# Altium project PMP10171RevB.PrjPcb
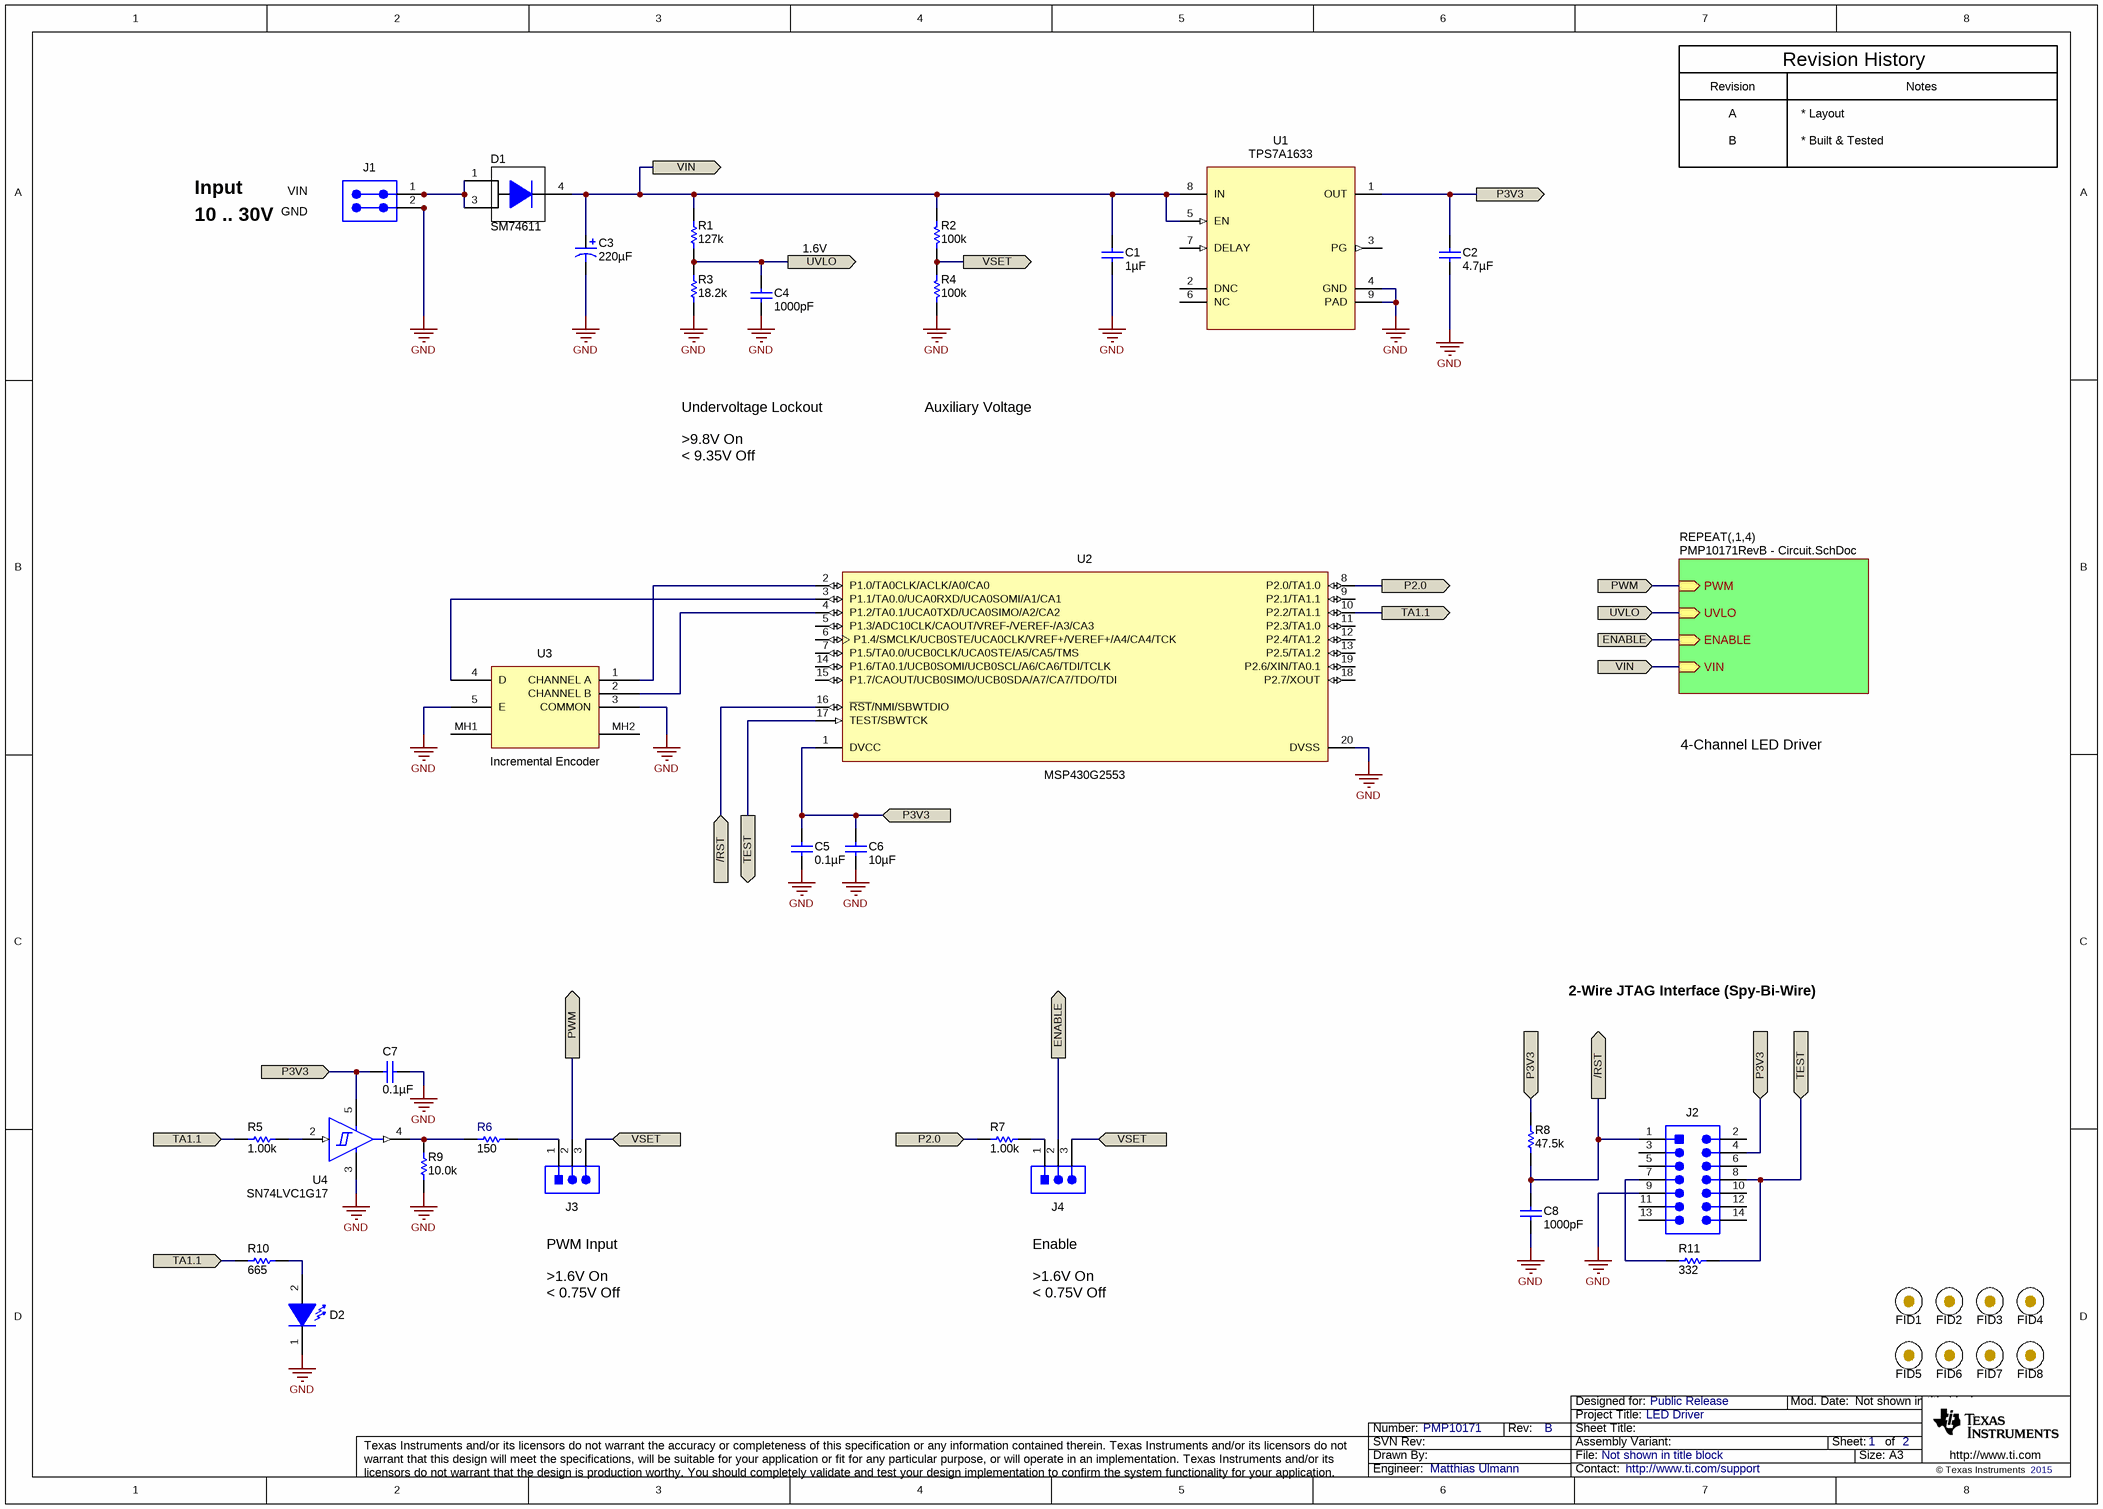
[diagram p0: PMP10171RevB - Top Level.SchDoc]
TechSupport: http://www.ti.com/support; SCH_Rev: B; PRJ_Title: LED Driver; PRJ_Number: PMP10171; PRJ_Engineer: Matthias Ulmann; PRJ_Customer: Public Release; PCB_Rev: A; PCB_Layout: M. Ulmann; CopyrightYear: 2015
2 sheets, 161 parts. Net scope: hierarchical (ports join the sheet entries above them; power ports are global).
Sheets:
  PMP10171RevB - Top Level.SchDoc
    1 = PMP10171RevB - Circuit.SchDoc
    2 = PMP10171RevB - Circuit.SchDoc
    3 = PMP10171RevB - Circuit.SchDoc
    4 = PMP10171RevB - Circuit.SchDoc

## Sheet PMP10171RevB - Top Level.SchDoc
size A3; Date: Not shown in title block; ApprovedBy: Not shown in title block; CheckedBy: Not shown in title block; Author: Not shown in title block; CompanyName: Not shown in title block; Engineer: Not shown in title block; Organization: Not shown in title block; Address1: Not shown in title block; Address2: Not shown in title block; Address3: Not shown in title block; Address4: Not shown in title block; DocumentNumber: 1; Revision: Use project parameter SCH_Rev; SheetNumber: 1; SheetTotal: 2; PageSetup: Record=PageOptions|CenterHorizontal=True|CenterVertical=True|PrintScale=0.97|XCorrection=1.00|YCorrection=1.00|PrintKind=0|BorderSize=5000000|LeftOffset=0|BottomOffset=0|Orientation=2|PaperLength=1000|PaperWidth=1000|Scale=100|PaperSource=15|PrintQuality=600|MediaType=1|DitherType=10|PaperKind=A4|PrintScaleMode=1

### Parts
C1  ValueDisplayed: 1µF  [1206]  (hidden comment: GRM31MR71H105KA88L)
C2  ValueDisplayed: 4.7µF  [0805_HV]  (hidden comment: GRM21BR71A475KA73L)
C3  ValueDisplayed: 220µF  [SM_RADIAL_G]  (hidden comment: EEE-FK1H221P)
C4  ValueDisplayed: 1000pF  [0603]  (hidden comment: GRM188R71H102KA01D)
C5  ValueDisplayed: 0.1µF  [0603]  (hidden comment: C0603C104K5RACTU)
C6  ValueDisplayed: 10µF  [0603]  (hidden comment: GRM188R60J106ME47D)
C7  ValueDisplayed: 0.1µF  [0603]  (hidden comment: C0603C104K5RACTU)
C8  ValueDisplayed: 1000pF  [0603]  (hidden comment: GRM188R71H102KA01D)
D1  SM74611  [DDPAK]
D2  150060SS75000  [WL-SMCW_RED]  (value not drawn)
FID1  Fiducial  [Fiducial10-30]  (value not drawn)
FID2  Fiducial  [Fiducial10-30]  (value not drawn)
FID3  Fiducial  [Fiducial10-30]  (value not drawn)
FID4  Fiducial  [Fiducial10-30]  (value not drawn)
FID5  Fiducial  [Fiducial10-30]  (value not drawn)
FID6  Fiducial  [Fiducial10-30]  (value not drawn)
FID7  Fiducial  [Fiducial10-30]  (value not drawn)
FID8  Fiducial  [Fiducial10-30]  (value not drawn)
J1  691 401 710 002B  [Wurth_691 401 710 002B]  (value not drawn)
J2  SBH11-PBPC-D07-ST-BK  [CONN_SBH11-PBPC-D07-ST-BK]  (value not drawn)
J3  61300311121  [WURTH_61300311121]  (value not drawn)
J4  61300311121  [WURTH_61300311121]  (value not drawn)
R1  ValueDisplayed: 127k  [0603]  (hidden comment: CRCW0603127KFKEA)
R2  ValueDisplayed: 100k  [0603]  (hidden comment: CRCW0603100KFKEA)
R3  ValueDisplayed: 18.2k  [0603]  (hidden comment: CRCW060318K2FKEA)
R4  ValueDisplayed: 100k  [0603]  (hidden comment: CRCW0603100KFKEA)
R5  ValueDisplayed: 1.00k  [0603]  (hidden comment: CRCW06031K00FKEA)
R6  ValueDisplayed: 150  [0603]  (hidden comment: CRCW0603150RFKEA)
R7  ValueDisplayed: 1.00k  [0603]  (hidden comment: CRCW06031K00FKEA)
R8  ValueDisplayed: 47.5k  [0603]  (hidden comment: CRCW060347K5FKEA)
R9  ValueDisplayed: 10.0k  [0603]  (hidden comment: CRCW060310K0FKEA)
R10  ValueDisplayed: 665  [0603]  (hidden comment: CRCW0603665RFKEA)
R11  ValueDisplayed: 332  [0603]  (hidden comment: CRCW0603332RFKEA)
U1  TPS7A1633  [DGN0008C_N]
U2  MSP430G2553  [PW0020A_N]
U3  Incremental Encoder  [Bourns_PEC16-2xxxF-Sxxx]
U4  SN74LVC1G17  [DCK0005A_N]

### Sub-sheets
REPEAT(,1,4) = PMP10171RevB - Circuit.SchDoc: PWM (in), UVLO (in), ENABLE (in), VIN (in)

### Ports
/RST (in), /RST (out), ENABLE, ENABLE (out), P2.0 (in), P2.0 (out), P3V3 (in), P3V3 (out), PWM, PWM (out), TA1.1 (in), TA1.1 (out), TEST (in), TEST (out), UVLO, UVLO (out), VIN, VIN (out), VSET (in), VSET (out)

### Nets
GND: C1.2 C2.2 C3.2(-) C4.2 C5.2 C6.2 C7.2 C8.2 D2.1(K) J1.2 J1.2A J2.9 R3.1 R4.1 R9.1 U1.4(GND) U1.9(PAD) U2.20(DVSS) U3.3(COMMON) U3.5(E) U4.3(GND)
/RST: C8.1 J2.1 R8.1 U2.16(~{RST}/NMI/SBWTDIO) ; port /RST
ENABLE: J4.2 ; port ENABLE, sheet REPEAT(,1,4)/ENABLE
P2.0: R7.1 U2.8(P2.0/TA1.0) ; port P2.0
P3V3: C2.1 C5.1 C6.1 C7.1 J2.4 R8.2 U1.1(OUT) U2.1(DVCC) U4.5(VCC) ; port P3V3
PWM: J3.2 ; port PWM, sheet REPEAT(,1,4)/PWM
TA1.1: R5.1 R10.1 U2.10(P2.2/TA1.1) ; port TA1.1
TEST: J2.8 R11.2 U2.17(TEST/SBWTCK) ; port TEST
UVLO: C4.1 R1.1 R3.2 ; port UVLO, sheet REPEAT(,1,4)/UVLO
VIN: C1.1 C3.1(+) D1.4(K) R1.2 R2.2 U1.5(EN) U1.8(IN) ; port VIN, sheet REPEAT(,1,4)/VIN
VSET: J3.3 J4.3 R2.1 R4.2 ; port VSET
NetD1_1: D1.1(A) D1.3(A) J1.1 J1.1A
NetD2_2: D2.2(A) R10.2
NetJ2_7: J2.7 R11.1
NetJ3_1: J3.1 R6.2
NetJ4_1: J4.1 R7.2
NetR5_2: R5.2 U4.2(A)
NetR6_1: R6.1 R9.2 U4.4(Y)
NetU2_2: U2.2(P1.0/TA0CLK/ACLK/A0/CA0) U3.1(CHANNEL_A)
NetU2_3: U2.3(P1.1/TA0.0/UCA0RXD/UCA0SOMI/A1/CA1) U3.4(D)
NetU2_4: U2.4(P1.2/TA0.1/UCA0TXD/UCA0SIMO/A2/CA2) U3.2(CHANNEL_B)

Not connected (* = marked no-connect by the designer): J2 2 3 5 6 10 11 12 13 14; U1 2(DNC) 3(PG) 6(NC) 7(DELAY); U2 5(P1.3/ADC10CLK/CAOUT/VREF-/VEREF-/A3/CA3) 6(P1.4/SMCLK/UCB0STE/UCA0CLK/VREF+/VEREF+/A4/CA4/TCK) 7(P1.5/TA0.0/UCB0CLK/UCA0STE/A5/CA5/TMS) 9(P2.1/TA1.1) 11(P2.3/TA1.0) 12(P2.4/TA1.2) 13(P2.5/TA1.2) 14(P1.6/TA0.1/UCB0SOMI/UCB0SCL/A6/CA6/TDI/TCLK) 15(P1.7/CAOUT/UCB0SIMO/UCB0SDA/A7/CA7/TDO/TDI) 18(P2.7/XOUT) 19(P2.6/XIN/TA0.1); U3 MH1 MH2

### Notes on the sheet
- Revision
- A
- * Layout
- Revision History
- Notes
- Input
- B
- * Built & Tested
- 10 .. 30V
- VIN
- GND
- (near C4) 1.6V
- Auxiliary Voltage
- Undervoltage Lockout
  >9.8V	On
  < 9.35V	Off
- 4-Channel LED Driver
- 2-Wire JTAG Interface (Spy-Bi-Wire)
- PWM Input
  >1.6V	On
  < 0.75V	Off
- Enable
  >1.6V	On
  < 0.75V	Off

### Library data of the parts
C1 = GRM31MR71H105KA88L: CAP, CERM, 1 µF, 50 V, +/- 10%, X7R, 1206; Manufacturer: MuRata; Polarized: N; CompType: Capacitor; Value: 1uF; U/M: EA; Cap_F: 0.000001; Tolerance_%: 10; Value1: Unknown; VDC_V: 50; Value2: 50V; TaMin_C: -55; TaMax_C: 125
C2 = GRM21BR71A475KA73L: CAP, CERM, 4.7 µF, 10 V, +/- 10%, X7R, 0805; Manufacturer: MuRata; Polarized: N; CompType: Capacitor; Value: 4.7uF; U/M: EA; Cap_F: 0.0000047; Tolerance_%: 10; Value1: Unknown; Value2: 10V; TaMin_C: -55; TaMax_C: 125; Cap_Case: 0805
C3 = EEE-FK1H221P: CAP, AL, 220 µF, 50 V, +/- 20%, 0.18 ohm, SMD; Manufacturer: Panasonic; Polarized: Y; CompType: Capacitor; Value: 220uF; U/M: EA; Cap_F: 0.00022; Tolerance_%: 20; VDC_V: 50; Value2: 50V; ESR_ohm: 0.18; IRMS_A: 0.67; TaMin_C: -55; TaMax_C: 105; Cap_Case: G
C4 C8 = GRM188R71H102KA01D: CAP, CERM, 1000 pF, 50 V, +/- 10%, X7R, 0603; Manufacturer: MuRata; Polarized: N; CompType: Capacitor; Value: 1000pF; U/M: EA; Cap_F: 0.000000001; Tolerance_%: 10; Value1: Unknown; VDC_V: 50; Value2: 50V; TaMin_C: -55; TaMax_C: 125
C5 C7 = C0603C104K5RACTU: CAP, CERM, 0.1 µF, 50 V, +/- 10%, X7R, 0603; Manufacturer: Kemet; Polarized: N; CompType: Capacitor; Value: 0.1uF; U/M: EA; Cap_F: 0.0000001; Tolerance_%: 10; Value1: Unknown; VDC_V: 50; Value2: 50V; TaMin_C: -55; TaMax_C: 125
C6 = GRM188R60J106ME47D: CAP, CERM, 10 µF, 6.3 V, +/- 20%, X5R, 0603; Manufacturer: MuRata; Polarized: N; CompType: Capacitor; Value: 10uF; U/M: EA; Cap_F: 0.00001; Tolerance_%: 20; ESR_ohm: 0.009; Value1: 0.009 ohm; VDC_V: 6.3; Value2: 6.3V; IRMS_A: 2.74; TaMin_C: -55; TaMax_C: 125
D1 = SM74611KTTR: Diode, P-N, 28 V, 15 A, DDPAK; Manufacturer: Texas Instruments; SymbolCreator: a0411947; U/M: EA; Vf_V: 0.026; Value: 28V; Value1: 15A; Value2: 0.026V; Io_A: 15; Vr_V: 28; TJmax_C: 125; RJC_CperW: 0.5
D2 = 150060SS75000: LED, Super Red, SMD; Manufacturer: Wurth Elektronik eiSos; Type: AlInGaP; Vf_V: 1.9; Value2: 1.9V; Io_A: 0.02; Value1: W; U/M: EA
FID1-FID8 = Fiducial: Fiducial mark.  There is nothing to buy or mount.; SymbolCreator: codlsc
J1 = 691 401 710 002B: Terminal Block, 1x2,  Tin, TH; Manufacturer: Wurth Elektronik; SymbolCreator: a0411947; U/M: EA
J2 = SBH11-PBPC-D07-ST-BK: Header (shrouded), 100 mil, 7x2, Gold, TH; Manufacturer: Sullins Connector Solutions; SymbolCreator: a0412235; U/M: EA
J3 J4 = 61300311121: Header, 2.54 mm, 3x1, Gold, TH; Manufacturer: Wurth Elektronik eiSos; SymbolCreator: a0799628; U/M: EA
R1 = CRCW0603127KFKEA: RES, 127 k, 1%, 0.1 W, 0603; Manufacturer: Vishay-Dale; CompType: Resistor; Value: 127k; Res_ohm: 127000; Tolerance_%: 1; Power_W: 0.1; Value2: 0.1W; VDC_V: 75; TempCo: 100 ppm/C; EIA_Code: E96; U/M: EA
R2 R4 = CRCW0603100KFKEA: RES, 100 k, 1%, 0.1 W, 0603; Manufacturer: Vishay-Dale; CompType: Resistor; Value: 100k; Res_ohm: 100000; Tolerance_%: 1; Power_W: 0.1; Value2: 0.1W; VDC_V: 75; TempCo: 100 ppm/C; EIA_Code: E96; U/M: EA
R3 = CRCW060318K2FKEA: RES, 18.2 k, 1%, 0.1 W, 0603; Manufacturer: Vishay-Dale; CompType: Resistor; Value: 18.2k; Res_ohm: 18200; Value_Code: 18k2; Tolerance_%: 1; Power_W: 0.1; Value2: 0.1W; VDC_V: 75; TempCo: 100 ppm/C; EIA_Code: E96; U/M: EA
R5 R7 = CRCW06031K00FKEA: RES, 1.00 k, 1%, 0.1 W, 0603; Manufacturer: Vishay-Dale; CompType: Resistor; Value: 1.00k; Res_ohm: 1000; Value_Code: 1k00; Tolerance_%: 1; Power_W: 0.1; Value2: 0.1W; VDC_V: 75; TempCo: 100 ppm/C; EIA_Code: E96; U/M: EA
R6 = CRCW0603150RFKEA: RES, 150, 1%, 0.1 W, 0603; Manufacturer: Vishay-Dale; CompType: Resistor; Value: 150; Value_Code: 150R; Tolerance_%: 1; Power_W: 0.1; Value2: 0.1W; VDC_V: 75; TempCo: 100 ppm/C; EIA_Code: E96; U/M: EA
R8 = CRCW060347K5FKEA: RES, 47.5 k, 1%, 0.1 W, 0603; Manufacturer: Vishay-Dale; CompType: Resistor; Value: 47.5k; Res_ohm: 47500; Value_Code: 47k5; Tolerance_%: 1; Power_W: 0.1; Value2: 0.1W; VDC_V: 75; TempCo: 100 ppm/C; EIA_Code: E96; U/M: EA
R9 = CRCW060310K0FKEA: RES, 10.0 k, 1%, 0.1 W, 0603; Manufacturer: Vishay-Dale; CompType: Resistor; Value: 10.0k; Res_ohm: 10000; Value_Code: 10k0; Tolerance_%: 1; Power_W: 0.1; Value2: 0.1W; VDC_V: 75; TempCo: 100 ppm/C; EIA_Code: E96; U/M: EA
R10 = CRCW0603665RFKEA: RES, 665, 1%, 0.1 W, 0603; Manufacturer: Vishay-Dale; CompType: Resistor; Value: 665; Value_Code: 665R; Tolerance_%: 1; Power_W: 0.1; Value2: 0.1W; VDC_V: 75; TempCo: 100 ppm/C; EIA_Code: E96; U/M: EA
R11 = CRCW0603332RFKEA: RES, 332, 1%, 0.1 W, 0603; Manufacturer: Vishay-Dale; CompType: Resistor; Value: 332; Value_Code: 332R; Tolerance_%: 1; Power_W: 0.1; Value2: 0.1W; VDC_V: 75; TempCo: 100 ppm/C; EIA_Code: E96; U/M: EA
U1 = TPS7A1633DGN: 60-V, 5-µA IQ, 100-mA, Low-Dropout Voltage Regulator with Enable and Power-Good, DGN0008C; Manufacturer: Texas Instruments; SymbolCreator: a0411947; CompType: IC; U/M: EA
U2 = MSP430G2553IPW20: Mixed Signal Microcontroller, PW0020A; Manufacturer: Texas Instruments; ADC: 10-bit SAR; ADC Channels: 8; Brown Out Reset: Yes; Eco-Plan: Green (RoHS & no Sb/Br); Flash(KB): 16; GPIO: 24; SRAM(B): 512; Timers - 16-bit: 2; USCI_A (UART/LIN/IrDA/SPI): 1; SymbolCreator: Altium/a0412235; CompType: IC; U/M: EA
U3 = PEC16-2220F-S0024: Rotary Encoder, 24 Pulse per Revolution, TH; Manufacturer: Bourns; SymbolCreator: Altium; CompType: SENSOR
U4 = SN74LVC1G17DCK: SINGLE SCHMITT-TRIGGER BUFFER, DCK0005A; Manufacturer: Texas Instruments; SymbolCreator: a0799628; CompType: IC; U/M: EA

## Sheet PMP10171RevB - Circuit.SchDoc
size A4; Date: Not shown in title block; ApprovedBy: Not shown in title block; CheckedBy: Not shown in title block; Author: Not shown in title block; CompanyName: Not shown in title block; Engineer: Not shown in title block; Organization: Not shown in title block; Address1: Not shown in title block; Address2: Not shown in title block; Address3: Not shown in title block; Address4: Not shown in title block; DocumentNumber: 2; Revision: Use project parameter SCH_Rev; SheetNumber: 2; SheetTotal: 2; PageSetup: Record=PageOptions|CenterHorizontal=True|CenterVertical=True|PrintScale=0.97|XCorrection=1.00|YCorrection=1.00|PrintKind=0|BorderSize=5000000|LeftOffset=0|BottomOffset=0|Orientation=2|PaperLength=1000|PaperWidth=1000|Scale=100|PaperSource=15|PrintQuality=600|MediaType=1|DitherType=10|PaperKind=A4|PrintScaleMode=1
Used 4 times, as channels 1, 2, 3, 4. Parts and nets are listed once, with the designators drawn on the sheet.
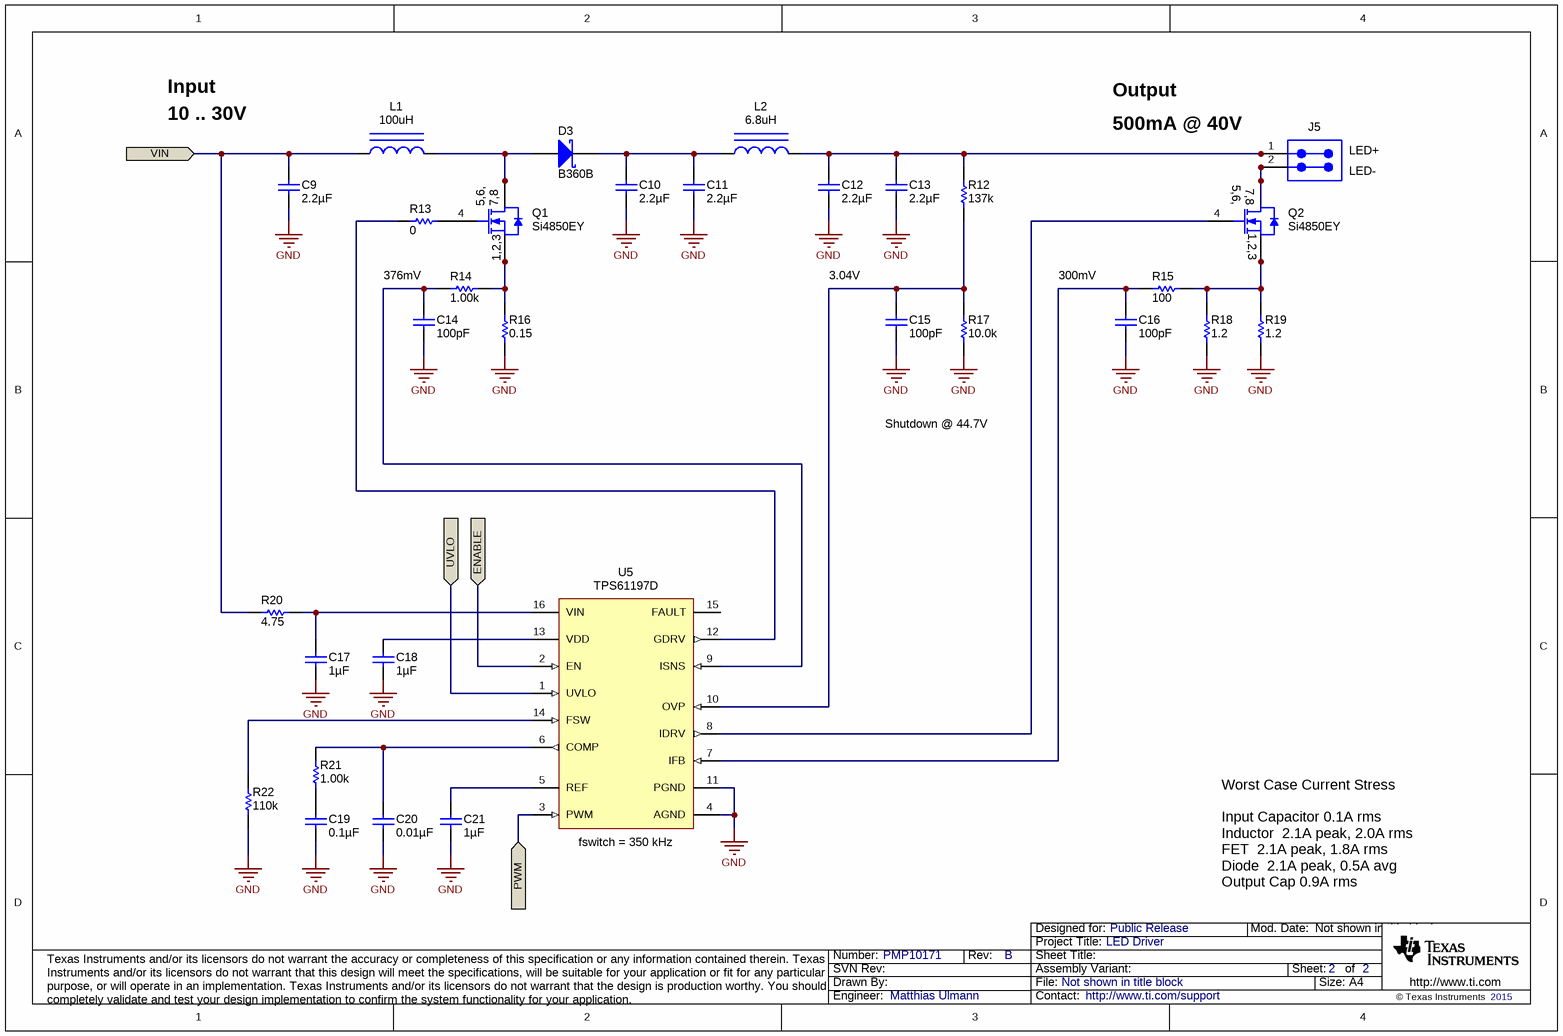
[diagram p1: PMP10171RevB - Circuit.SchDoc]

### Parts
C9  ValueDisplayed: 2.2µF  [1210]  (hidden comment: GRM32ER72A225KA35L)
C10  ValueDisplayed: 2.2µF  [1210]  (hidden comment: GRM32ER72A225KA35L)
C11  ValueDisplayed: 2.2µF  [1210]  (hidden comment: GRM32ER72A225KA35L)
C12  ValueDisplayed: 2.2µF  [1210]  (hidden comment: GRM32ER72A225KA35L)
C13  ValueDisplayed: 2.2µF  [1210]  (hidden comment: GRM32ER72A225KA35L)
C14  ValueDisplayed: 100pF  [0603]  (hidden comment: GRM1885C1H101JA01D)
C15  ValueDisplayed: 100pF  [0603]  (hidden comment: GRM1885C1H101JA01D)
C16  ValueDisplayed: 100pF  [0603]  (hidden comment: GRM1885C1H101JA01D)
C17  ValueDisplayed: 1µF  [1206]  (hidden comment: GRM31MR71H105KA88L)
C18  ValueDisplayed: 1µF  [0603]  (hidden comment: GRM188R71E105KA12D)
C19  ValueDisplayed: 0.1µF  [0603]  (hidden comment: GCM188R71H104KA57D)
C20  ValueDisplayed: 0.01µF  [0603]  (hidden comment: GRM188R71H103KA01D)
C21  ValueDisplayed: 1µF  [0603]  (hidden comment: GRM188R71E105KA12D)
D3  B360B  [SMB]
J5  691 401 710 002B  [Wurth_691 401 710 002B]  (value not drawn)
L1  100uH  [WE-PD_1280]
L2  6.8uH  [WE-TPC-S]
Q1  Si4850EY  [SOIC-8]
Q2  Si4850EY  [SOIC-8]
R12  ValueDisplayed: 137k  [0603]  (hidden comment: CRCW0603137KFKEA)
R13  ValueDisplayed: 0  [0603]  (hidden comment: CRCW06030000Z0EA)
R14  ValueDisplayed: 1.00k  [0603]  (hidden comment: CRCW06031K00FKEA)
R15  ValueDisplayed: 100  [0603]  (hidden comment: CRCW0603100RFKEA)
R16  ValueDisplayed: 0.15  [2010]  (hidden comment: CSR2010FTR150)
R17  ValueDisplayed: 10.0k  [0603]  (hidden comment: CRCW060310K0FKEA)
R18  ValueDisplayed: 1.2  [1206]  (hidden comment: CRCW12061R20JNEA)
R19  ValueDisplayed: 1.2  [1206]  (hidden comment: CRCW12061R20JNEA)
R20  ValueDisplayed: 4.75  [0603]  (hidden comment: CRCW06034R75FKEA)
R21  ValueDisplayed: 1.00k  [0603]  (hidden comment: CRCW06031K00FKEA)
R22  ValueDisplayed: 110k  [0603]  (hidden comment: CRCW0603110KFKEA)
U5  TPS61197D  [D0016A_N]

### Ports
ENABLE (in), PWM (in), UVLO (in), VIN (in)

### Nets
GND: C9.2 C10.2 C11.2 C12.2 C13.2 C14.2 C15.2 C16.2 C17.2 C18.1 C19.2 C20.2 C21.2 R16.1 R17.1 R18.1 R19.1 R22.1 U5.4(AGND) U5.11(PGND)
ENABLE: U5.2(EN) ; port ENABLE
PWM: U5.3(PWM) ; port PWM
UVLO: U5.1(UVLO) ; port UVLO
VIN: C9.1 L1.1 R20.1 ; port VIN
NetC10_1: C10.1 C11.1 D3.1(K) L2.1
NetC12_1: C12.1 C13.1 J5.1 J5.1A L2.2 R12.2
NetC14_1: C14.1 R14.2 U5.9(ISNS)
NetC15_1: C15.1 R12.1 R17.2 U5.10(OVP)
NetC16_1: C16.1 R15.1 U5.7(IFB)
NetC17_1: C17.1 R20.2 U5.16(VIN)
NetC18_2: C18.2 U5.13(VDD)
NetC19_1: C19.1 R21.1
NetC20_1: C20.1 R21.2 U5.6(COMP)
NetC21_1: C21.1 U5.5(REF)
NetD3_2: D3.2(A) L1.2 Q1.5(D) Q1.6(D) Q1.7(D) Q1.8(D)
NetJ5_2: J5.2 J5.2A Q2.5(D) Q2.6(D) Q2.7(D) Q2.8(D)
NetQ1_1: Q1.1(S) Q1.2(S) Q1.3(S) R14.1 R16.2
NetQ1_4: Q1.4(G) R13.1
NetQ2_1: Q2.1(S) Q2.2(S) Q2.3(S) R15.2 R18.2 R19.2
NetQ2_4: Q2.4(G) U5.8(IDRV)
NetR13_2: R13.2 U5.12(GDRV)
NetR22_2: R22.2 U5.14(FSW)

Not connected (* = marked no-connect by the designer): U5 15(FAULT)

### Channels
1: designators end in -1; ports ENABLE=ENABLE PWM=PWM UVLO=UVLO VIN=VIN
2: designators end in -2; ports ENABLE=ENABLE PWM=PWM UVLO=UVLO VIN=VIN
3: designators end in -3; ports ENABLE=ENABLE PWM=PWM UVLO=UVLO VIN=VIN
4: designators end in -4; ports ENABLE=ENABLE PWM=PWM UVLO=UVLO VIN=VIN

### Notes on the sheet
- 10 .. 30V
- Input
- Output
- 500mA @ 40V
- LED+
- LED-
- 376mV
- 3.04V
- 300mV
- Shutdown @ 44.7V
- (near U5) fswitch = 350 kHz
- Worst Case Current Stress
  Input Capacitor	0.1A rms
  Inductor		2.1A peak, 2.0A rms
  FET		2.1A peak, 1.8A rms
  Diode		2.1A peak, 0.5A avg
  Output Cap	0.9A rms

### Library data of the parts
C9-C13 = GRM32ER72A225KA35L: CAP, CERM, 2.2 µF, 100 V, +/- 10%, X7R, 1210; Manufacturer: MuRata; Polarized: N; CompType: Capacitor; Value: 2.2uF; U/M: EA; Cap_F: 0.0000022; Tolerance_%: 10; ESR_ohm: 0.007; Value1: 0.007 ohm; VDC_V: 100; Value2: 100V; IRMS_A: 4.4; TaMin_C: -55; TaMax_C: 125
C14-C16 = GRM1885C1H101JA01D: CAP, CERM, 100 pF, 50 V, +/- 5%, C0G/NP0, 0603; Manufacturer: MuRata; Polarized: N; CompType: Capacitor; Value: 100pF; U/M: EA; Cap_F: 0.0000000001; Tolerance_%: 5; Value1: Unknown; VDC_V: 50; Value2: 50V; TaMin_C: -55; TaMax_C: 125
C17 = GRM31MR71H105KA88L: as C1 on sheet PMP10171RevB - Top Level
C18 C21 = GRM188R71E105KA12D: CAP, CERM, 1 µF, 25 V, +/- 10%, X7R, 0603; Manufacturer: MuRata; Polarized: N; CompType: Capacitor; Value: 1uF; U/M: EA; Cap_F: 0.000001; Tolerance_%: 10; Value1: Unknown; VDC_V: 25; Value2: 25V; TaMin_C: -55; TaMax_C: 125
C19 = GCM188R71H104KA57D: CAP, CERM, 0.1 µF, 50 V, +/- 10%, X7R, 0603; Manufacturer: MuRata; Polarized: N; CompType: Capacitor; Value: 0.1uF; U/M: EA; Cap_F: 0.0000001; Tolerance_%: 10; ESR_ohm: 0.02; Value1: 0.02 ohm; VDC_V: 50; Value2: 50V; IRMS_A: 1.84; TaMin_C: -55; TaMax_C: 125
C20 = GRM188R71H103KA01D: CAP, CERM, 0.01 µF, 50 V, +/- 10%, X7R, 0603; Manufacturer: MuRata; Polarized: N; CompType: Capacitor; Value: 0.01uF; U/M: EA; Cap_F: 0.00000001; Tolerance_%: 10; Value1: Unknown; VDC_V: 50; Value2: 50V; TaMin_C: -55; TaMax_C: 125
D3 = B360B-13-F: Diode, Schottky, 60 V, 3 A, SMB; Manufacturer: Diodes Inc.; U/M: EA; Vf_V: 0.7; Value: 60V; Value1: 3A; Value2: 0.7V; Io_A: 3; Vr_V: 60; TJmax_C: 125; RJC_CperW: 25
J5 = 691 401 710 002B: as J1 on sheet PMP10171RevB - Top Level
L1 = 74477020: Inductor, Shielded Drum Core, Ferrite, 100 µH, 2.2 A, 0.102 ohm, SMD; Manufacturer: Wurth Elektronik eiSos; Ind_H: 100.0E-6; ValueDisplayed: 100µH; Imax_A: 2.2; Irms: 2.2A @ 40C rise; Isat: 2.4A @ 10% inductance drop; DCR_ohm: 0.102; Value2: 2.2A
L2 = 744031006: Inductor, Shielded Drum Core, Ferrite, 6.8 µH, 0.75 A, 0.135 ohm, SMD; Manufacturer: Wurth Elektronik eiSos; Ind_H: 6.8E-6; ValueDisplayed: 6.8µH; Imax_A: 0.75; Irms: 0.85A @ 30C rise; Isat: 0.75A @ 35% inductance drop; DCR_ohm: 0.135; Value2: 0.75A
Q1 Q2 = SI4850EY-T1-E3: MOSFET, N-CH, 60 V, 6 A, SOIC-8; Manufacturer: Vishay-Siliconix; Alternate Manufacturer: None; U/M: EA; ChType: N; Value: 60V; VdsMax_V: 60; Value1: 0.025 ohm; Rdson45_ohm: 0.025; Value2: 18 nC; QgTyp_nC: 18; Vgs_V: 20; IdsMax_A: 6
R12 = CRCW0603137KFKEA: RES, 137 k, 1%, 0.1 W, 0603; Manufacturer: Vishay-Dale; CompType: Resistor; Value: 137k; Res_ohm: 137000; Tolerance_%: 1; Power_W: 0.1; Value2: 0.1W; VDC_V: 75; TempCo: 100 ppm/C; EIA_Code: E96; U/M: EA
R13 = CRCW06030000Z0EA: RES, 0, 5%, 0.1 W, 0603; Manufacturer: Vishay-Dale; CompType: Resistor; Value: 0; Value_Code: 0000; Tolerance_%: 5; Power_W: 0.1; Value2: 0.1W; VDC_V: 75; TempCo: 200 ppm/C; EIA_Code: E24; U/M: EA
R14 R21 = CRCW06031K00FKEA: as R5 on sheet PMP10171RevB - Top Level
R15 = CRCW0603100RFKEA: RES, 100, 1%, 0.1 W, 0603; Manufacturer: Vishay-Dale; CompType: Resistor; Value: 100; Value_Code: 100R; Tolerance_%: 1; Power_W: 0.1; Value2: 0.1W; VDC_V: 75; TempCo: 100 ppm/C; EIA_Code: E96; U/M: EA
R16 = CSR2010FTR150: RES, 0.15, 1%, 1 W, 2010; Manufacturer: Stackpole Electronics Inc; CompType: Resistor; Value: 0.15; Value_Code: R150; Tolerance_%: 1; Value2: 1W; TempCo: 100 ppm/C; EIA_Code: E96; U/M: EA
R17 = CRCW060310K0FKEA: as R9 on sheet PMP10171RevB - Top Level
R18 R19 = CRCW12061R20JNEA: RES, 1.2, 5%, 0.25 W, 1206; Manufacturer: Vishay-Dale; CompType: Resistor; Value: 1.2; Value_Code: 1R20; Tolerance_%: 5; Power_W: 0.25; Value2: 0.25W; VDC_V: 200; TempCo: 200 ppm/C; EIA_Code: E24; U/M: EA
R20 = CRCW06034R75FKEA: RES, 4.75, 1%, 0.1 W, 0603; Manufacturer: Vishay-Dale; CompType: Resistor; Value: 4.75; Value_Code: 4R75; Tolerance_%: 1; Power_W: 0.1; Value2: 0.1W; VDC_V: 75; TempCo: 100 ppm/C; EIA_Code: E96; U/M: EA
R22 = CRCW0603110KFKEA: RES, 110 k, 1%, 0.1 W, 0603; Manufacturer: Vishay-Dale; CompType: Resistor; Value: 110k; Res_ohm: 110000; Tolerance_%: 1; Power_W: 0.1; Value2: 0.1W; VDC_V: 75; TempCo: 100 ppm/C; EIA_Code: E96; U/M: EA
U5 = TPS61197D: Single-String WLED Driver for LCD TV, D0016A; Manufacturer: Texas Instruments; SymbolCreator: x0208325; CompType: IC; U/M: EA

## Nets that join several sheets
GND: PMP10171RevB - Top Level (21 pins), 1 (20 pins), 2 (20 pins), 3 (20 pins), 4 (20 pins)
ENABLE: PMP10171RevB - Top Level (J4.2), 1 (U5-1.2), 2 (U5-2.2), 3 (U5-3.2), 4 (U5-4.2)
PWM: PMP10171RevB - Top Level (J3.2), 1 (U5-1.3), 2 (U5-2.3), 3 (U5-3.3), 4 (U5-4.3)
UVLO: PMP10171RevB - Top Level (C4.1 R1.1 R3.2), 1 (U5-1.1), 2 (U5-2.1), 3 (U5-3.1), 4 (U5-4.1)
VIN: PMP10171RevB - Top Level (7 pins), 1 (C9-1.1 L1-1.1 R20-1.1), 2 (C9-2.1 L1-2.1 R20-2.1), 3 (C9-3.1 L1-3.1 R20-3.1), 4 (C9-4.1 L1-4.1 R20-4.1)

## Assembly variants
001: all parts fitted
